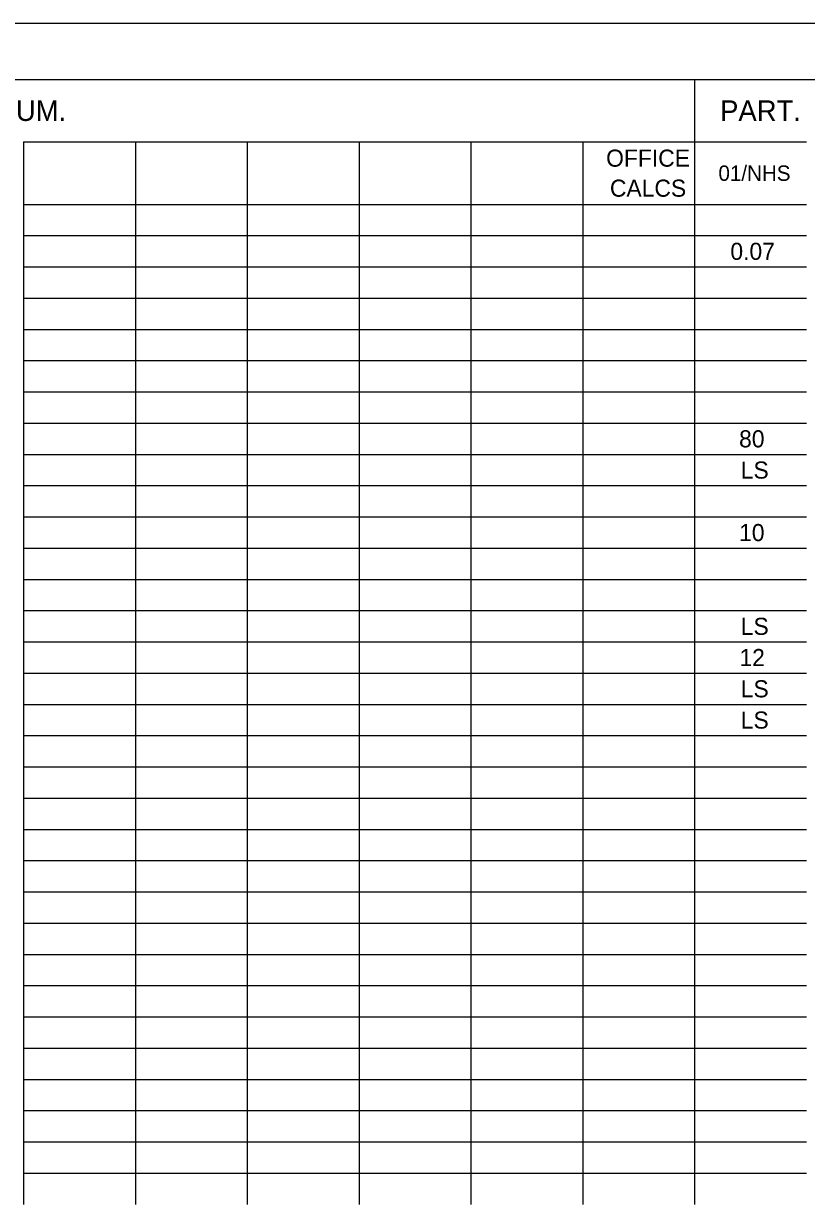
# Model space of a CAD drawing. Extents: x 0 to 34, y 0 to 22.
# Drawn here: x 8.52 to 15.54, y 11.42 to 22 of the extents above; entities that cross this region are included whole.
import ezdxf

# ---------------------------------------------------------------- set-up
doc = ezdxf.new("R2010")
doc.units = 0
for name, color, linetype in [('SH_Border', 7, 'Continuous'), ('SH_Cut_Line', 7, 'Continuous'), ('SH_Text', 7, 'Continuous')]:
    doc.layers.add(name, color=color, linetype=linetype)

msp = doc.modelspace()

# ---------------------------------------------------------------- linework, layer by layer
at = {"layer": 'SH_Border'}
msp.add_lwpolyline([(1.5, 21.5), (33.5, 21.5), (33.5, 0.5), (1.5, 0.5)], close=True, dxfattribs=at)
at = {"layer": 'SH_Cut_Line'}
msp.add_lwpolyline([(0, 0), (34, 0), (34, 22), (0, 22)], close=True, dxfattribs=at)
at = {"layer": 'SH_Text'}
for p, q in [((8.518, 21.5), (9.52, 21.5)), ((9.52, 21.5), (11.525, 21.5)), ((11.525, 21.5), (12.528, 21.5)), ((12.528, 21.5), (13.53, 21.5)), ((13.53, 21.5), (14.533, 21.5)), ((14.533, 21.5), (15.535, 21.5)), ((14.533, 21.5), (14.533, 21.22)), ((14.533, 21.22), (14.533, 20.94)), ((8.518, 20.94), (9.52, 20.94)), ((8.518, 20.94), (8.518, 20.66)), ((9.52, 20.94), (11.525, 20.94)), ((9.52, 20.94), (9.52, 20.66)), ((10.523, 20.94), (10.523, 20.66)), ((11.525, 20.94), (12.528, 20.94)), ((11.525, 20.94), (11.525, 20.66)), ((12.528, 20.94), (13.53, 20.94)), ((12.528, 20.94), (12.528, 20.66)), ((13.53, 20.94), (14.533, 20.94)), ((13.53, 20.94), (13.53, 20.66)), ((14.533, 20.94), (15.535, 20.94)), ((14.533, 20.94), (14.533, 20.66)), ((8.518, 20.66), (8.518, 20.38)), ((9.52, 20.66), (9.52, 20.38)), ((10.523, 20.66), (10.523, 20.38)), ((11.525, 20.66), (11.525, 20.38)), ((12.528, 20.66), (12.528, 20.38)), ((13.53, 20.66), (13.53, 20.38)), ((14.533, 20.66), (14.533, 20.38)), ((8.518, 20.38), (9.52, 20.38)), ((8.518, 20.38), (8.518, 20.1)), ((9.52, 20.38), (11.525, 20.38)), ((9.52, 20.38), (9.52, 20.1)), ((10.523, 20.38), (10.523, 20.1)), ((11.525, 20.38), (12.528, 20.38)), ((11.525, 20.38), (11.525, 20.1)), ((12.528, 20.38), (13.53, 20.38)), ((12.528, 20.38), (12.528, 20.1)), ((13.53, 20.38), (14.533, 20.38)), ((13.53, 20.38), (13.53, 20.1)), ((14.533, 20.38), (15.535, 20.38)), ((14.533, 20.38), (14.533, 20.1)), ((8.518, 20.1), (9.52, 20.1)), ((8.518, 20.1), (8.518, 18.7)), ((9.52, 20.1), (11.525, 20.1)), ((9.52, 20.1), (9.52, 18.7)), ((10.523, 20.1), (10.523, 18.7)), ((11.525, 20.1), (12.528, 20.1)), ((11.525, 20.1), (11.525, 18.7)), ((12.528, 20.1), (13.53, 20.1)), ((12.528, 20.1), (12.528, 18.7)), ((13.53, 20.1), (14.533, 20.1)), ((13.53, 20.1), (13.53, 18.7)), ((14.533, 20.1), (15.535, 20.1)), ((14.533, 20.1), (14.533, 18.7)), ((8.518, 19.82), (9.52, 19.82)), ((9.52, 19.82), (11.525, 19.82)), ((11.525, 19.82), (12.528, 19.82)), ((12.528, 19.82), (13.53, 19.82)), ((13.53, 19.82), (14.533, 19.82)), ((14.533, 19.82), (15.535, 19.82)), ((8.518, 19.54), (9.52, 19.54)), ((9.52, 19.54), (11.525, 19.54)), ((11.525, 19.54), (12.528, 19.54)), ((12.528, 19.54), (13.53, 19.54)), ((13.53, 19.54), (14.533, 19.54)), ((14.533, 19.54), (15.535, 19.54)), ((8.518, 19.26), (9.52, 19.26)), ((9.52, 19.26), (11.525, 19.26)), ((11.525, 19.26), (12.528, 19.26)), ((12.528, 19.26), (13.53, 19.26)), ((13.53, 19.26), (14.533, 19.26)), ((14.533, 19.26), (15.535, 19.26)), ((8.518, 18.98), (9.52, 18.98)), ((9.52, 18.98), (11.525, 18.98)), ((11.525, 18.98), (12.528, 18.98)), ((12.528, 18.98), (13.53, 18.98)), ((13.53, 18.98), (14.533, 18.98)), ((14.533, 18.98), (15.535, 18.98)), ((8.518, 18.7), (9.52, 18.7)), ((8.518, 18.7), (8.518, 18.14)), ((9.52, 18.7), (11.525, 18.7)), ((9.52, 18.7), (9.52, 18.14)), ((10.523, 18.7), (10.523, 18.14)), ((11.525, 18.7), (12.528, 18.7)), ((11.525, 18.7), (11.525, 18.14)), ((12.528, 18.7), (13.53, 18.7)), ((12.528, 18.7), (12.528, 18.14)), ((13.53, 18.7), (14.533, 18.7)), ((13.53, 18.7), (13.53, 18.14)), ((14.533, 18.7), (15.535, 18.7)), ((14.533, 18.7), (14.533, 18.14)), ((8.518, 18.42), (9.52, 18.42)), ((9.52, 18.42), (11.525, 18.42)), ((11.525, 18.42), (12.528, 18.42)), ((12.528, 18.42), (13.53, 18.42)), ((13.53, 18.42), (14.533, 18.42)), ((14.533, 18.42), (15.535, 18.42)), ((8.518, 18.14), (9.52, 18.14)), ((8.518, 18.14), (8.518, 17.86)), ((9.52, 18.14), (11.525, 18.14)), ((9.52, 18.14), (9.52, 17.86)), ((10.523, 18.14), (10.523, 17.86)), ((11.525, 18.14), (12.528, 18.14)), ((11.525, 18.14), (11.525, 17.86)), ((12.528, 18.14), (13.53, 18.14)), ((12.528, 18.14), (12.528, 17.86)), ((13.53, 18.14), (14.533, 18.14)), ((13.53, 18.14), (13.53, 17.86)), ((14.533, 18.14), (15.535, 18.14)), ((14.533, 18.14), (14.533, 17.86)), ((8.518, 17.86), (9.52, 17.86)), ((8.518, 17.86), (8.518, 17.58)), ((9.52, 17.86), (11.525, 17.86)), ((9.52, 17.86), (9.52, 17.58)), ((10.523, 17.86), (10.523, 17.58)), ((11.525, 17.86), (12.528, 17.86)), ((11.525, 17.86), (11.525, 17.58)), ((12.528, 17.86), (13.53, 17.86)), ((12.528, 17.86), (12.528, 17.58)), ((13.53, 17.86), (14.533, 17.86)), ((13.53, 17.86), (13.53, 17.58)), ((14.533, 17.86), (15.535, 17.86)), ((14.533, 17.86), (14.533, 17.58)), ((8.518, 17.58), (9.52, 17.58)), ((8.518, 17.58), (8.518, 17.3)), ((9.52, 17.58), (11.525, 17.58)), ((9.52, 17.58), (9.52, 17.3)), ((10.523, 17.58), (10.523, 17.3)), ((11.525, 17.58), (12.528, 17.58)), ((11.525, 17.58), (11.525, 17.3)), ((12.528, 17.58), (13.53, 17.58)), ((12.528, 17.58), (12.528, 17.3)), ((13.53, 17.58), (14.533, 17.58)), ((13.53, 17.58), (13.53, 17.3)), ((14.533, 17.58), (15.535, 17.58)), ((14.533, 17.58), (14.533, 17.3)), ((8.518, 17.3), (9.52, 17.3)), ((8.518, 17.3), (8.518, 17.02)), ((9.52, 17.3), (11.525, 17.3)), ((9.52, 17.3), (9.52, 17.02)), ((10.523, 17.3), (10.523, 17.02)), ((11.525, 17.3), (12.528, 17.3)), ((11.525, 17.3), (11.525, 17.02)), ((12.528, 17.3), (13.53, 17.3)), ((12.528, 17.3), (12.528, 17.02)), ((13.53, 17.3), (14.533, 17.3)), ((13.53, 17.3), (13.53, 17.02)), ((14.533, 17.3), (15.535, 17.3)), ((14.533, 17.3), (14.533, 17.02)), ((8.518, 17.02), (9.52, 17.02)), ((8.518, 17.02), (8.518, 16.74)), ((9.52, 17.02), (11.525, 17.02)), ((9.52, 17.02), (9.52, 16.74)), ((10.523, 17.02), (10.523, 16.74)), ((11.525, 17.02), (12.528, 17.02)), ((11.525, 17.02), (11.525, 16.74)), ((12.528, 17.02), (13.53, 17.02)), ((12.528, 17.02), (12.528, 16.74)), ((13.53, 17.02), (14.533, 17.02)), ((13.53, 17.02), (13.53, 16.74)), ((14.533, 17.02), (15.535, 17.02)), ((14.533, 17.02), (14.533, 16.74)), ((8.518, 16.74), (9.52, 16.74)), ((8.518, 16.74), (8.518, 16.18)), ((9.52, 16.74), (11.525, 16.74)), ((9.52, 16.74), (9.52, 16.18)), ((10.523, 16.74), (10.523, 16.18)), ((11.525, 16.74), (12.528, 16.74)), ((11.525, 16.74), (11.525, 16.18)), ((12.528, 16.74), (13.53, 16.74)), ((12.528, 16.74), (12.528, 16.18)), ((13.53, 16.74), (14.533, 16.74)), ((13.53, 16.74), (13.53, 16.18)), ((14.533, 16.74), (15.535, 16.74)), ((14.533, 16.74), (14.533, 16.18)), ((8.518, 16.46), (9.52, 16.46)), ((9.52, 16.46), (11.525, 16.46)), ((11.525, 16.46), (12.528, 16.46)), ((12.528, 16.46), (13.53, 16.46)), ((13.53, 16.46), (14.533, 16.46)), ((14.533, 16.46), (15.535, 16.46)), ((8.518, 16.18), (9.52, 16.18)), ((8.518, 16.18), (8.518, 15.9)), ((9.52, 16.18), (11.525, 16.18)), ((9.52, 16.18), (9.52, 15.9)), ((10.523, 16.18), (10.523, 15.9)), ((11.525, 16.18), (12.528, 16.18)), ((11.525, 16.18), (11.525, 15.9)), ((12.528, 16.18), (13.53, 16.18)), ((12.528, 16.18), (12.528, 15.9)), ((13.53, 16.18), (14.533, 16.18)), ((13.53, 16.18), (13.53, 15.9)), ((14.533, 16.18), (15.535, 16.18)), ((14.533, 16.18), (14.533, 15.9)), ((8.518, 15.9), (9.52, 15.9)), ((8.518, 15.9), (8.518, 15.62)), ((9.52, 15.9), (11.525, 15.9)), ((9.52, 15.9), (9.52, 15.62)), ((10.523, 15.9), (10.523, 15.62)), ((11.525, 15.9), (12.528, 15.9)), ((11.525, 15.9), (11.525, 15.62)), ((12.528, 15.9), (13.53, 15.9)), ((12.528, 15.9), (12.528, 15.62)), ((13.53, 15.9), (14.533, 15.9)), ((13.53, 15.9), (13.53, 15.62)), ((14.533, 15.9), (15.535, 15.9)), ((14.533, 15.9), (14.533, 15.62)), ((8.518, 15.62), (9.52, 15.62)), ((8.518, 15.62), (8.518, 15.34)), ((9.52, 15.62), (11.525, 15.62)), ((9.52, 15.62), (9.52, 15.34)), ((10.523, 15.62), (10.523, 15.34)), ((11.525, 15.62), (12.528, 15.62)), ((11.525, 15.62), (11.525, 15.34)), ((12.528, 15.62), (13.53, 15.62)), ((12.528, 15.62), (12.528, 15.34)), ((13.53, 15.62), (14.533, 15.62)), ((13.53, 15.62), (13.53, 15.34)), ((14.533, 15.62), (15.535, 15.62)), ((14.533, 15.62), (14.533, 15.34)), ((8.518, 15.34), (9.52, 15.34)), ((8.518, 15.34), (8.518, 14.78)), ((9.52, 15.34), (11.525, 15.34)), ((9.52, 15.34), (9.52, 14.78)), ((10.523, 15.34), (10.523, 14.78)), ((11.525, 15.34), (12.528, 15.34)), ((11.525, 15.34), (11.525, 14.78)), ((12.528, 15.34), (13.53, 15.34)), ((12.528, 15.34), (12.528, 14.78)), ((13.53, 15.34), (14.533, 15.34)), ((13.53, 15.34), (13.53, 14.78)), ((14.533, 15.34), (15.535, 15.34)), ((14.533, 15.34), (14.533, 14.78)), ((8.518, 15.06), (9.52, 15.06)), ((9.52, 15.06), (11.525, 15.06)), ((11.525, 15.06), (12.528, 15.06)), ((12.528, 15.06), (13.53, 15.06)), ((13.53, 15.06), (14.533, 15.06)), ((14.533, 15.06), (15.535, 15.06)), ((8.518, 14.78), (9.52, 14.78)), ((8.518, 14.78), (8.518, 14.5)), ((9.52, 14.78), (11.525, 14.78)), ((9.52, 14.78), (9.52, 14.5)), ((10.523, 14.78), (10.523, 14.5)), ((11.525, 14.78), (12.528, 14.78)), ((11.525, 14.78), (11.525, 14.5)), ((12.528, 14.78), (13.53, 14.78)), ((12.528, 14.78), (12.528, 14.5)), ((13.53, 14.78), (14.533, 14.78)), ((13.53, 14.78), (13.53, 14.5)), ((14.533, 14.78), (15.535, 14.78)), ((14.533, 14.78), (14.533, 14.5)), ((8.518, 14.5), (9.52, 14.5)), ((8.518, 14.5), (8.518, 14.22)), ((9.52, 14.5), (11.525, 14.5)), ((9.52, 14.5), (9.52, 14.22)), ((10.523, 14.5), (10.523, 14.22)), ((11.525, 14.5), (12.528, 14.5)), ((11.525, 14.5), (11.525, 14.22)), ((12.528, 14.5), (13.53, 14.5)), ((12.528, 14.5), (12.528, 14.22)), ((13.53, 14.5), (14.533, 14.5)), ((13.53, 14.5), (13.53, 14.22)), ((14.533, 14.5), (15.535, 14.5)), ((14.533, 14.5), (14.533, 14.22)), ((8.518, 14.22), (9.52, 14.22)), ((8.518, 14.22), (8.518, 13.94)), ((9.52, 14.22), (11.525, 14.22)), ((9.52, 14.22), (9.52, 13.94)), ((10.523, 14.22), (10.523, 13.94)), ((11.525, 14.22), (12.528, 14.22)), ((11.525, 14.22), (11.525, 13.94)), ((12.528, 14.22), (13.53, 14.22)), ((12.528, 14.22), (12.528, 13.94)), ((13.53, 14.22), (14.533, 14.22)), ((13.53, 14.22), (13.53, 13.94)), ((14.533, 14.22), (15.535, 14.22)), ((14.533, 14.22), (14.533, 13.94)), ((8.518, 13.94), (9.52, 13.94)), ((8.518, 13.94), (8.518, 11.7)), ((9.52, 13.94), (11.525, 13.94)), ((9.52, 13.94), (9.52, 11.7)), ((10.523, 13.94), (10.523, 11.7)), ((11.525, 13.94), (12.528, 13.94)), ((11.525, 13.94), (11.525, 11.7)), ((12.528, 13.94), (13.53, 13.94)), ((12.528, 13.94), (12.528, 11.7)), ((13.53, 13.94), (14.533, 13.94)), ((13.53, 13.94), (13.53, 11.7)), ((14.533, 13.94), (15.535, 13.94)), ((14.533, 13.94), (14.533, 11.7)), ((8.518, 13.66), (9.52, 13.66)), ((9.52, 13.66), (11.525, 13.66)), ((11.525, 13.66), (12.528, 13.66)), ((12.528, 13.66), (13.53, 13.66)), ((13.53, 13.66), (14.533, 13.66)), ((14.533, 13.66), (15.535, 13.66)), ((8.518, 13.38), (9.52, 13.38)), ((9.52, 13.38), (11.525, 13.38)), ((11.525, 13.38), (12.528, 13.38)), ((12.528, 13.38), (13.53, 13.38)), ((13.53, 13.38), (14.533, 13.38)), ((14.533, 13.38), (15.535, 13.38)), ((8.518, 13.1), (9.52, 13.1)), ((9.52, 13.1), (11.525, 13.1)), ((11.525, 13.1), (12.528, 13.1)), ((12.528, 13.1), (13.53, 13.1)), ((13.53, 13.1), (14.533, 13.1)), ((14.533, 13.1), (15.535, 13.1)), ((8.518, 12.82), (9.52, 12.82)), ((9.52, 12.82), (11.525, 12.82)), ((11.525, 12.82), (12.528, 12.82)), ((12.528, 12.82), (13.53, 12.82)), ((13.53, 12.82), (14.533, 12.82)), ((14.533, 12.82), (15.535, 12.82)), ((8.518, 12.54), (9.52, 12.54)), ((9.52, 12.54), (11.525, 12.54)), ((11.525, 12.54), (12.528, 12.54)), ((12.528, 12.54), (13.53, 12.54)), ((13.53, 12.54), (14.533, 12.54)), ((14.533, 12.54), (15.535, 12.54)), ((8.518, 12.26), (9.52, 12.26)), ((9.52, 12.26), (11.525, 12.26)), ((11.525, 12.26), (12.528, 12.26)), ((12.528, 12.26), (13.53, 12.26)), ((13.53, 12.26), (14.533, 12.26)), ((14.533, 12.26), (15.535, 12.26)), ((8.518, 11.98), (9.52, 11.98)), ((9.52, 11.98), (11.525, 11.98)), ((11.525, 11.98), (12.528, 11.98)), ((12.528, 11.98), (13.53, 11.98)), ((13.53, 11.98), (14.533, 11.98)), ((14.533, 11.98), (15.535, 11.98)), ((8.518, 11.7), (9.52, 11.7)), ((8.518, 11.7), (8.518, 11.42)), ((9.52, 11.7), (11.525, 11.7)), ((9.52, 11.7), (9.52, 11.42)), ((10.523, 11.7), (10.523, 11.42)), ((11.525, 11.7), (12.528, 11.7)), ((11.525, 11.7), (11.525, 11.42)), ((12.528, 11.7), (13.53, 11.7)), ((12.528, 11.7), (12.528, 11.42)), ((13.53, 11.7), (14.533, 11.7)), ((13.53, 11.7), (13.53, 11.42)), ((14.533, 11.7), (15.535, 11.7)), ((14.533, 11.7), (14.533, 11.42))]:
    msp.add_line(p, q, dxfattribs=at)

# ---------------------------------------------------------------- texts
for s, height, p in [('SHEET NUM.', 0.184, (7.382, 21.128)), ('PART.', 0.184, (14.762, 21.128)), ('OFFICE ', 0.1533, (13.74, 20.718)), ('01/NHS', 0.138, (14.747, 20.591)), ('CALCS', 0.1533, (13.774, 20.449)), ('0.07', 0.1533, (14.854, 19.883)), ('80', 0.1533, (14.932, 18.203)), ('LS', 0.1533, (14.947, 17.923)), ('10', 0.1533, (14.932, 17.363)), ('LS', 0.1533, (14.947, 16.523)), ('12', 0.1533, (14.935, 16.243)), ('LS', 0.1533, (14.947, 15.963)), ('LS', 0.1533, (14.947, 15.683))]:
    msp.add_text(s, height=height, dxfattribs=at).set_placement(p)

doc.saveas('drawing.dxf')
